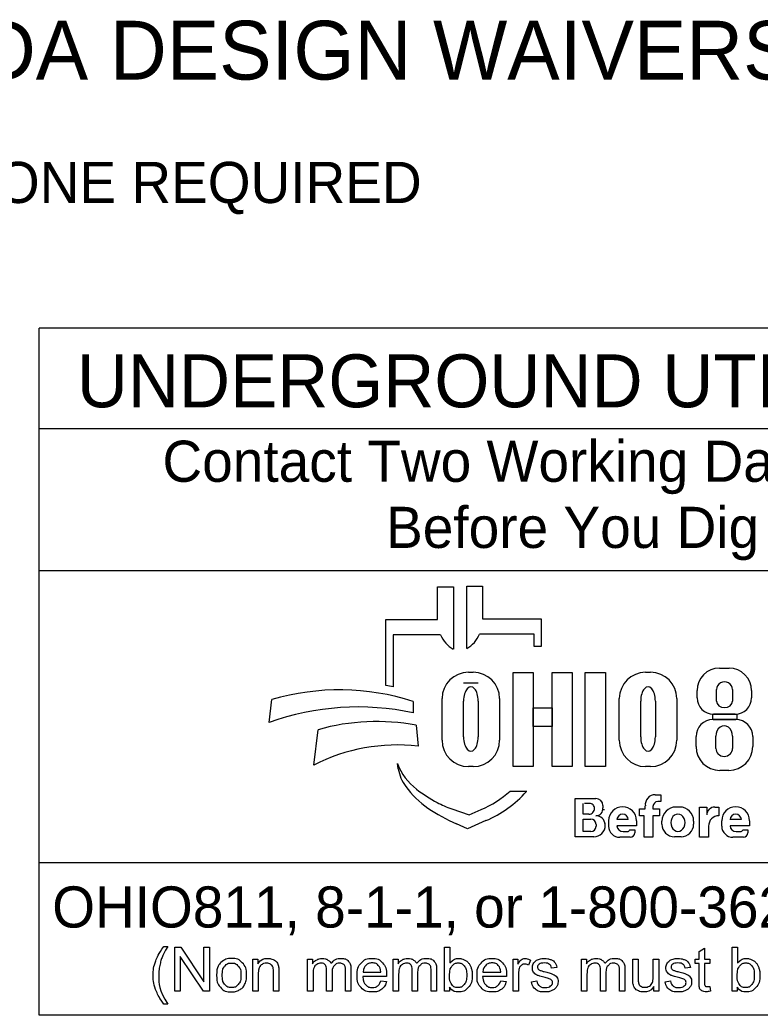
# Model space of a CAD drawing. Extents: x 0 to 48.6, y 0 to 22.
# Drawn here: x 2.312 to 4.831, y 2.143 to 5.529 of the extents above; entities that cross this region are included whole.
import ezdxf

# ---------------------------------------------------------------- set-up
doc = ezdxf.new("R2010")
doc.units = 0
doc.layers.add('SH_Data', color=7, linetype='Continuous')
doc.layers.add('SH_Text', color=7, linetype='Continuous')

msp = doc.modelspace()

# ---------------------------------------------------------------- linework, layer by layer
at = {"layer": 'SH_Data'}
for p, q in [((2.3775, 2.1428), (2.3775, 4.4803)), ((6.6275, 4.4803), (2.3775, 4.4803)), ((2.3775, 4.1387), (6.6275, 4.1387)), ((2.3775, 3.6553), (6.6275, 3.6553)), ((6.6275, 2.6607), (2.3775, 2.6607)), ((6.6275, 2.1428), (2.3775, 2.1428))]:
    msp.add_line(p, q, dxfattribs=at)
at = {"layer": 'SH_Text'}
for p, q in [((3.7335, 3.4883), (3.7335, 3.5998)), ((3.7335, 3.5998), (3.7872, 3.5998)), ((3.7872, 3.5998), (3.7872, 3.3877)), ((3.8329, 3.39), (3.8329, 3.6021)), ((3.8329, 3.6021), (3.8865, 3.6021)), ((3.8865, 3.6021), (3.8865, 3.4906)), ((3.5576, 3.2644), (3.5576, 3.4883)), ((3.5576, 3.4883), (3.7335, 3.4883)), ((3.8865, 3.4906), (4.0857, 3.4906)), ((4.0857, 3.4906), (4.0857, 3.3968)), ((3.5828, 3.4369), (3.5828, 3.26)), ((3.7439, 3.4369), (3.5828, 3.4369)), ((4.0625, 3.4392), (3.8761, 3.4392)), ((4.0625, 3.3968), (4.0625, 3.4392)), ((4.0857, 3.3968), (4.0625, 3.3968)), ((4.6931, 3.3231), (4.7258, 3.3231)), ((3.8385, 3.3091), (3.8551, 3.3091)), ((4.4416, 3.3091), (4.4581, 3.3091)), ((3.8718, 3.2721), (3.822, 3.2721)), ((4.683, 3.2111), (4.683, 3.2504)), ((4.7371, 3.2504), (4.7371, 3.2111)), ((3.7491, 3.0776), (3.7491, 3.2196)), ((3.9445, 3.2196), (3.9445, 3.0776)), ((4.3521, 3.0776), (4.3521, 3.2196)), ((4.5476, 3.2196), (4.5476, 3.0776)), ((4.6168, 3.2225), (4.6168, 3.2468)), ((4.8022, 3.2468), (4.8022, 3.2225)), ((3.1602, 3.1381), (3.1696, 3.2162)), ((3.6509, 3.2097), (3.6509, 3.1709)), ((3.822, 3.089), (3.822, 3.2114)), ((3.8718, 3.2114), (3.8718, 3.089)), ((4.425, 3.089), (4.425, 3.2114)), ((4.4748, 3.2114), (4.4748, 3.089)), ((4.7462, 3.1665), (4.6728, 3.1665)), ((3.6608, 3.1291), (3.6671, 3.0582)), ((4.671, 3.1482), (4.7483, 3.1482)), ((3.312, 2.9936), (3.3267, 3.1137)), ((4.6131, 3.0563), (4.6131, 3.0903)), ((4.6806, 3.0503), (4.6806, 3.0912)), ((4.7374, 3.0912), (4.7374, 3.0503)), ((4.8062, 3.0903), (4.8062, 3.0563)), ((3.5997, 2.9807), (3.5967, 2.9986)), ((3.8551, 2.9882), (3.8385, 2.9882)), ((4.4581, 2.9882), (4.4416, 2.9882)), ((4.7252, 2.9753), (4.6941, 2.9753)), ((3.98, 2.9048), (4.0375, 2.9048)), ((4.2013, 2.749), (4.2013, 2.8798)), ((4.2013, 2.8798), (4.2725, 2.8798)), ((4.4739, 2.8926), (4.4934, 2.8926)), ((4.4934, 2.8926), (4.4934, 2.8696)), ((3.7816, 2.8444), (3.841, 2.8239)), ((4.2293, 2.8263), (4.2293, 2.8632)), ((4.2545, 2.8632), (4.2332, 2.8632)), ((4.2963, 2.856), (4.2963, 2.8481)), ((4.4213, 2.8212), (4.4213, 2.8442)), ((4.4213, 2.8442), (4.4406, 2.8442)), ((4.4406, 2.8442), (4.4406, 2.8546)), ((4.4667, 2.8526), (4.4667, 2.8442)), ((4.4667, 2.8442), (4.4883, 2.8442)), ((4.4934, 2.8691), (4.4832, 2.8691)), ((4.4883, 2.8442), (4.4883, 2.8212)), ((4.5451, 2.8508), (4.5573, 2.8508)), ((4.6254, 2.7478), (4.6254, 2.8505)), ((4.6254, 2.8505), (4.6499, 2.8505)), ((4.6499, 2.8505), (4.6499, 2.8237)), ((4.6772, 2.8505), (4.691, 2.8505)), ((4.691, 2.8505), (4.691, 2.8209)), ((3.841, 2.8239), (3.8821, 2.8417)), ((4.2487, 2.8263), (4.2293, 2.8263)), ((4.4362, 2.8212), (4.4213, 2.8212)), ((4.4362, 2.7478), (4.4362, 2.8212)), ((4.4883, 2.8212), (4.4667, 2.8212)), ((4.4667, 2.8212), (4.4667, 2.7478)), ((3.835, 2.7769), (3.7976, 2.7934)), ((3.8983, 2.8044), (3.835, 2.7769)), ((4.2293, 2.7669), (4.2293, 2.8097)), ((4.2293, 2.8097), (4.2548, 2.8097)), ((4.2729, 2.7916), (4.2729, 2.7853)), ((4.3043, 2.7887), (4.3043, 2.7884)), ((4.3159, 2.7858), (4.3159, 2.8042)), ((4.3824, 2.8082), (4.3439, 2.8082)), ((4.4104, 2.7866), (4.344, 2.7866)), ((4.4104, 2.8042), (4.4104, 2.7866)), ((4.4973, 2.7922), (4.4973, 2.8029)), ((4.6051, 2.8029), (4.6051, 2.7922)), ((4.6559, 2.786), (4.6559, 2.7478)), ((4.7008, 2.7858), (4.7008, 2.8042)), ((4.7674, 2.8082), (4.7288, 2.8082)), ((4.7953, 2.7866), (4.7289, 2.7866)), ((4.7953, 2.8042), (4.7953, 2.7866)), ((4.265, 2.749), (4.2013, 2.749)), ((4.2546, 2.7669), (4.2293, 2.7669)), ((4.3892, 2.7478), (4.3538, 2.7478)), ((4.3649, 2.7673), (4.379, 2.7673)), ((4.3876, 2.7729), (4.4045, 2.7729)), ((4.4045, 2.7729), (4.4045, 2.7631)), ((4.4667, 2.7478), (4.4362, 2.7478)), ((4.5623, 2.7494), (4.5401, 2.7494)), ((4.6559, 2.7478), (4.6254, 2.7478)), ((4.7742, 2.7478), (4.7388, 2.7478)), ((4.7498, 2.7673), (4.7639, 2.7673)), ((4.7725, 2.7729), (4.7894, 2.7729)), ((4.7894, 2.7729), (4.7894, 2.7631))]:
    msp.add_line(p, q, dxfattribs=at)
for points in [[(3.991, 3.3081), (4.0589, 3.3081), (4.0589, 2.9881), (3.991, 2.9881)], [(4.1231, 3.3081), (4.1911, 3.3081), (4.1911, 2.9881), (4.1231, 2.9881)], [(4.2364, 3.3081), (4.3052, 3.3081), (4.3052, 2.9881), (4.2364, 2.9881)], [(4.0589, 3.1882), (4.1231, 3.1882), (4.1231, 3.1242), (4.0589, 3.1242)], [(4.6706, 3.1665), (4.7523, 3.1665), (4.7523, 3.1481), (4.6706, 3.1481)]]:
    msp.add_lwpolyline(points, close=True, dxfattribs=at)
for points in [[(2.8021, 2.3766), (2.8153, 2.3766)], [(2.8389, 2.2239), (2.8389, 2.3741), (2.8592, 2.3741), (2.9382, 2.2561), (2.9382, 2.3741), (2.9572, 2.3741), (2.9572, 2.2239), (2.9369, 2.2239), (2.8579, 2.3419), (2.8579, 2.2239), (2.8389, 2.2239)], [(3.7743, 2.2239), (3.7573, 2.2239), (3.7573, 2.3741), (3.7757, 2.3741), (3.7757, 2.3206)], [(4.6233, 2.2558), (4.6233, 2.3185), (4.6097, 2.3185), (4.6097, 2.3328), (4.6233, 2.3328), (4.6233, 2.3597), (4.6417, 2.3708), (4.6417, 2.3328), (4.6601, 2.3328), (4.6601, 2.3185), (4.6417, 2.3185), (4.6417, 2.2547)], [(4.7534, 2.2239), (4.7363, 2.2239), (4.7363, 2.3741), (4.7548, 2.3741), (4.7548, 2.3206)], [(3.1048, 2.2239), (3.1048, 2.3328), (3.1214, 2.3328), (3.1214, 2.3173)], [(3.2912, 2.2239), (3.2912, 2.3328), (3.3077, 2.3328), (3.3077, 2.3174)], [(3.5826, 2.2239), (3.5826, 2.3328), (3.5991, 2.3328), (3.5991, 2.3174)], [(3.9904, 2.2239), (3.9904, 2.3328), (4.007, 2.3328), (4.007, 2.3163)], [(4.0495, 2.3293), (4.043, 2.3122)], [(4.1394, 2.3046), (4.1213, 2.3022)], [(4.2236, 2.2239), (4.2236, 2.3328), (4.2401, 2.3328), (4.2401, 2.3174)], [(4.3979, 2.2654), (4.3979, 2.3328), (4.4164, 2.3328), (4.4164, 2.2724)], [(4.4676, 2.2745), (4.4676, 2.3328), (4.4861, 2.3328), (4.4861, 2.2239), (4.4696, 2.2239)], [(4.594, 2.3046), (4.5759, 2.3022)], [(3.1233, 2.2833), (3.1233, 2.2239), (3.1048, 2.2239)], [(3.1932, 2.2908), (3.1932, 2.2239), (3.1748, 2.2239), (3.1748, 2.2901)], [(3.3097, 2.2803), (3.3097, 2.2239), (3.2912, 2.2239)], [(3.3743, 2.2871), (3.3743, 2.2239), (3.3559, 2.2239), (3.3559, 2.2946)], [(3.4388, 2.2986), (3.4388, 2.2239), (3.4203, 2.2239), (3.4203, 2.2924)], [(3.56, 2.2736), (3.4788, 2.2736)], [(3.4799, 2.2887), (3.5406, 2.2887)], [(3.601, 2.2803), (3.601, 2.2239), (3.5826, 2.2239)], [(3.6657, 2.2871), (3.6657, 2.2239), (3.6473, 2.2239), (3.6473, 2.2946)], [(3.7301, 2.2986), (3.7301, 2.2239), (3.7117, 2.2239), (3.7117, 2.2924)], [(3.968, 2.2736), (3.8868, 2.2736)], [(3.8879, 2.2887), (3.9486, 2.2887)], [(4.0088, 2.2809), (4.0088, 2.2239), (3.9904, 2.2239)], [(4.242, 2.2803), (4.242, 2.2239), (4.2236, 2.2239)], [(4.3067, 2.2871), (4.3067, 2.2239), (4.2883, 2.2239), (4.2883, 2.2946)], [(4.3711, 2.2986), (4.3711, 2.2239), (4.3527, 2.2239), (4.3527, 2.2924)], [(3.5404, 2.2591), (3.5595, 2.2567)], [(3.7743, 2.2375), (3.7743, 2.2239)], [(3.9484, 2.2591), (3.9675, 2.2567)], [(4.053, 2.2564), (4.0712, 2.2593)], [(4.4696, 2.2239), (4.4696, 2.24)], [(4.5076, 2.2564), (4.5258, 2.2593)], [(4.6601, 2.2404), (4.6628, 2.2241)], [(4.7534, 2.2375), (4.7534, 2.2239)], [(2.8153, 2.1798), (2.8021, 2.1798)]]:
    msp.add_lwpolyline(points, dxfattribs=at)
for centre, radius, start, end in [((3.8353, 3.4736), 0.0985, 201.9296, 240.7469), ((3.7847, 3.476), 0.0985, 299.2531, 338.0704), ((4.6931, 3.2468), 0.0763, 90, 180), ((4.7258, 3.2468), 0.0763, 0, 90), ((3.8385, 3.2196), 0.0895, 90, 180), ((3.8551, 3.2196), 0.0895, 0, 90), ((4.4416, 3.2196), 0.0895, 90, 180), ((4.4581, 3.2196), 0.0895, 0, 90), ((3.4295, 2.4554), 0.8191, 79.2074, 81.0007), ((3.3997, 2.4302), 0.8191, 72.1402, 106.3144), ((4.6728, 3.2225), 0.056, 180, 270), ((4.7462, 3.2225), 0.056, 270, 0), ((3.4628, 2.2991), 0.8919, 77.8238, 109.8274), ((3.5267, 2.4094), 0.7322, 79.44, 105.8467), ((4.671, 3.0903), 0.0579, 90, 180), ((4.7483, 3.0903), 0.0579, 0, 90), ((3.5987, 2.4262), 0.6357, 83.8248, 116.8021), ((3.8385, 3.0776), 0.0895, 180, 270), ((3.8551, 3.0776), 0.0895, 270, 0), ((4.4416, 3.0776), 0.0895, 180, 270), ((4.4581, 3.0776), 0.0895, 270, 0), ((4.6941, 3.0563), 0.081, 180, 270), ((4.7252, 3.0563), 0.081, 270, 0), ((3.7841, 3.0707), 0.2008, 201.0457, 232.5314), ((3.741, 3.0048), 0.1433, 189.6817, 216.0884), ((3.8747, 3.1022), 0.3088, 216.0884, 235.7167), ((3.9766, 3.3219), 0.5173, 232.5314, 241.794), ((3.7387, 3.1722), 0.3602, 293.4582, 312.0712), ((3.7387, 3.1722), 0.401, 293.4582, 317.8286), ((4.2725, 2.856), 0.0238, 0, 90), ((4.4739, 2.859), 0.0335, 90, 187.5187), ((4.0412, 3.3465), 0.6044, 235.7167, 246.2325), ((3.8914, 3.1631), 0.3371, 241.794, 250.9821), ((4.2487, 2.845), 0.0187, 270, 2.0582), ((4.2505, 2.8463), 0.0169, 357.8325, 90), ((4.2721, 2.8453), 0.0243, 270, 6.6529), ((4.3631, 2.8042), 0.0473, 0, 180), ((4.4832, 2.8526), 0.0165, 90, 180), ((4.5451, 2.8029), 0.0478, 90, 180), ((4.5573, 2.8029), 0.0478, 0, 90), ((4.6768, 2.8237), 0.0269, 89.2449, 180), ((4.7481, 2.8042), 0.0473, 0, 180), ((4.2722, 2.7889), 0.0321, 4.0748, 90), ((4.2827, 2.8438), 0.0175, 347.4023, 0), ((4.3632, 2.8072), 0.0193, 2.9632, 177.0368), ((4.6908, 2.786), 0.0349, 89.6033, 180), ((4.7481, 2.8072), 0.0193, 2.9632, 177.0368), ((4.2546, 2.7853), 0.0184, 270, 0), ((4.2548, 2.7916), 0.0181, 0, 90), ((4.265, 2.7884), 0.0393, 270, 0), ((4.2714, 2.7887), 0.033, 0, 11.7502), ((4.3538, 2.7858), 0.038, 180, 270), ((4.3649, 2.7883), 0.021, 184.827, 270), ((4.5401, 2.7922), 0.0428, 180, 270), ((4.5623, 2.7922), 0.0428, 270, 0), ((4.7388, 2.7858), 0.038, 180, 270), ((4.7498, 2.7883), 0.021, 184.827, 270), ((4.379, 2.7767), 0.00938, 270, 335.9979), ((4.3892, 2.7631), 0.0152, 270, 0), ((4.7639, 2.7767), 0.00938, 270, 335.9979), ((4.7742, 2.7631), 0.0152, 270, 0)]:
    msp.add_arc(centre, radius, start, end, dxfattribs=at)
for centre, major_axis, ratio, start_param, end_param in [((3.8469, 3.2114), (0, 0.0484), 0.514403, 4.712389, 7.853982), ((4.4499, 3.2114), (0, 0.0484), 0.514403, 4.712389, 7.853982), ((4.71, 3.2504), (0.0271, 0), 0.969373, 0, 3.141593), ((4.71, 3.2111), (0.0271, 0), 0.818453, 3.141593, 6.283185), ((4.709, 3.0912), (0, 0.0358), 0.794529, 4.712389, 7.853982), ((3.8469, 3.089), (0, 0.0484), 0.514403, 1.570796, 4.712389), ((4.4499, 3.089), (0, 0.0484), 0.514403, 1.570796, 4.712389), ((4.709, 3.0503), (0.0284, 0), 0.959837, 3.141593, 6.283185), ((4.5517, 2.7976), (0, 0.029), 0.832186, 4.712389, 7.853982), ((4.5517, 2.7976), (0, 0.0302), 0.797287, 1.570796, 4.712389)]:
    msp.add_ellipse(centre, major_axis=major_axis, ratio=ratio, start_param=start_param, end_param=end_param, dxfattribs=at)
for points in [[(2.8021, 2.1798), (2.7869, 2.199), (2.7763, 2.2248), (2.7657, 2.2506), (2.7657, 2.2783), (2.7657, 2.3026), (2.7736, 2.325), (2.7829, 2.3509), (2.8021, 2.3766)], [(2.8153, 2.3766), (2.8029, 2.3553), (2.7989, 2.3462), (2.7927, 2.332), (2.7891, 2.3167), (2.7847, 2.2975), (2.7847, 2.2782), (2.7847, 2.2289), (2.8153, 2.1798)], [(2.9814, 2.2783), (2.9814, 2.3085), (2.9981, 2.3231), (3.0122, 2.3352), (3.0323, 2.3352), (3.0547, 2.3352), (3.069, 2.3205), (3.0832, 2.3058), (3.0832, 2.2799), (3.0832, 2.2589), (3.0769, 2.2469), (3.0706, 2.2348), (3.0586, 2.2282), (3.0466, 2.2215), (3.0323, 2.2215), (3.0095, 2.2215), (2.9954, 2.2362), (2.9814, 2.2508), (2.9814, 2.2783)], [(3.0003, 2.2783), (3.0003, 2.2574), (3.0094, 2.247), (3.0185, 2.2366), (3.0323, 2.2366), (3.046, 2.2366), (3.0551, 2.2471), (3.0642, 2.2575), (3.0642, 2.279), (3.0642, 2.2991), (3.0551, 2.3095), (3.0459, 2.3199), (3.0323, 2.3199), (3.0185, 2.3199), (3.0094, 2.3096), (3.0003, 2.2992), (3.0003, 2.2783)], [(3.1214, 2.3173), (3.1334, 2.3352), (3.156, 2.3352), (3.1659, 2.3352), (3.1741, 2.3316), (3.1823, 2.3281), (3.1864, 2.3224), (3.1905, 2.3166), (3.1922, 2.3087), (3.1932, 2.3036), (3.1932, 2.2908)], [(3.1748, 2.2901), (3.1748, 2.3013), (3.1726, 2.3069), (3.1705, 2.3125), (3.165, 2.3158), (3.1595, 2.3191), (3.1521, 2.3191), (3.1404, 2.3191), (3.1318, 2.3117), (3.1233, 2.3042), (3.1233, 2.2833)], [(3.3077, 2.3174), (3.3128, 2.3254), (3.3214, 2.3303), (3.3299, 2.3352), (3.3407, 2.3352), (3.3528, 2.3352), (3.3606, 2.3301), (3.3683, 2.3251), (3.3715, 2.3161), (3.3844, 2.3352), (3.4051, 2.3352), (3.4213, 2.3352), (3.43, 2.3262), (3.4388, 2.3172), (3.4388, 2.2986)], [(3.3559, 2.2946), (3.3559, 2.3069), (3.3514, 2.313), (3.3469, 2.3191), (3.3366, 2.3191), (3.3288, 2.3191), (3.3222, 2.315), (3.3156, 2.311), (3.3126, 2.3031), (3.3097, 2.2952), (3.3097, 2.2803)], [(3.4203, 2.2924), (3.4203, 2.3035), (3.4185, 2.3083), (3.4168, 2.3132), (3.412, 2.3162), (3.4073, 2.3191), (3.401, 2.3191), (3.3895, 2.3191), (3.3819, 2.3115), (3.3743, 2.3039), (3.3743, 2.2871)], [(3.5595, 2.2567), (3.555, 2.24), (3.5428, 2.2307), (3.5306, 2.2215), (3.5117, 2.2215), (3.4878, 2.2215), (3.4738, 2.2362), (3.4598, 2.2509), (3.4598, 2.2774), (3.4598, 2.3049), (3.474, 2.32), (3.4881, 2.3352), (3.5106, 2.3352), (3.5324, 2.3352), (3.5463, 2.3203), (3.5601, 2.3055), (3.5601, 2.2785), (3.5601, 2.2769), (3.56, 2.2736)], [(3.5406, 2.2887), (3.5394, 2.3025), (3.5337, 2.3094), (3.5249, 2.3201), (3.5108, 2.3201), (3.4981, 2.3201), (3.4894, 2.3115), (3.4808, 2.303), (3.4799, 2.2887)], [(3.5991, 2.3174), (3.6042, 2.3254), (3.6127, 2.3303), (3.6212, 2.3352), (3.6321, 2.3352), (3.6442, 2.3352), (3.6519, 2.3301), (3.6597, 2.3251), (3.6628, 2.3161), (3.6758, 2.3352), (3.6965, 2.3352), (3.7127, 2.3352), (3.7214, 2.3262), (3.7301, 2.3172), (3.7301, 2.2986)], [(3.6473, 2.2946), (3.6473, 2.3069), (3.6428, 2.313), (3.6383, 2.3191), (3.628, 2.3191), (3.6202, 2.3191), (3.6136, 2.315), (3.607, 2.311), (3.604, 2.3031), (3.601, 2.2952), (3.601, 2.2803)], [(3.7117, 2.2924), (3.7117, 2.3035), (3.7099, 2.3083), (3.7081, 2.3132), (3.7034, 2.3162), (3.6987, 2.3191), (3.6923, 2.3191), (3.6809, 2.3191), (3.6733, 2.3115), (3.6657, 2.3039), (3.6657, 2.2871)], [(3.7741, 2.2792), (3.7741, 2.2596), (3.7794, 2.2509), (3.7881, 2.2366), (3.8029, 2.2366), (3.815, 2.2366), (3.8238, 2.2471), (3.8326, 2.2576), (3.8326, 2.2784), (3.8326, 2.2998), (3.8241, 2.3099), (3.8157, 2.3201), (3.8038, 2.3201), (3.7917, 2.3201), (3.7829, 2.3096), (3.7741, 2.299), (3.7741, 2.2792)], [(3.7757, 2.3206), (3.7874, 2.3352), (3.8055, 2.3352), (3.8155, 2.3352), (3.8245, 2.3311), (3.8335, 2.3271), (3.8392, 2.3198), (3.845, 2.3124), (3.8483, 2.3021), (3.8516, 2.2918), (3.8516, 2.28), (3.8516, 2.252), (3.8378, 2.2368), (3.8239, 2.2215), (3.8046, 2.2215), (3.7853, 2.2215), (3.7743, 2.2375)], [(3.9675, 2.2567), (3.963, 2.24), (3.9508, 2.2307), (3.9386, 2.2215), (3.9196, 2.2215), (3.8958, 2.2215), (3.8818, 2.2362), (3.8678, 2.2509), (3.8678, 2.2774), (3.8678, 2.3049), (3.882, 2.32), (3.8961, 2.3352), (3.9186, 2.3352), (3.9404, 2.3352), (3.9543, 2.3203), (3.9681, 2.3055), (3.9681, 2.2785), (3.9681, 2.2769), (3.968, 2.2736)], [(3.9486, 2.2887), (3.9474, 2.3025), (3.9417, 2.3094), (3.9328, 2.3201), (3.9188, 2.3201), (3.9061, 2.3201), (3.8974, 2.3115), (3.8888, 2.303), (3.8879, 2.2887)], [(4.007, 2.3163), (4.0133, 2.3278), (4.0187, 2.3315), (4.0241, 2.3352), (4.0305, 2.3352), (4.0398, 2.3352), (4.0495, 2.3293)], [(4.043, 2.3122), (4.0363, 2.3162), (4.0295, 2.3162), (4.0235, 2.3162), (4.0187, 2.3125), (4.0139, 2.3089), (4.0119, 2.3024), (4.0088, 2.2926), (4.0088, 2.2809)], [(4.1213, 2.3022), (4.1201, 2.3106), (4.1142, 2.3153), (4.1083, 2.3201), (4.0975, 2.3201), (4.0848, 2.3201), (4.0794, 2.3159), (4.0739, 2.3116), (4.0739, 2.306), (4.0739, 2.3024), (4.0762, 2.2995), (4.0785, 2.2966), (4.0833, 2.2946), (4.086, 2.2936), (4.0996, 2.2899), (4.1192, 2.2847), (4.1269, 2.2813), (4.1347, 2.278), (4.1391, 2.2717), (4.1435, 2.2653), (4.1435, 2.2559), (4.1435, 2.2467), (4.1381, 2.2386), (4.1327, 2.2304), (4.1226, 2.226), (4.1124, 2.2215), (4.0996, 2.2215), (4.0784, 2.2215), (4.0672, 2.2303), (4.0561, 2.2391), (4.053, 2.2564)], [(4.0712, 2.2593), (4.0727, 2.2483), (4.0798, 2.2425), (4.0868, 2.2366), (4.0995, 2.2366), (4.1122, 2.2366), (4.1184, 2.2418), (4.1245, 2.247), (4.1245, 2.254), (4.1245, 2.2602), (4.1191, 2.2638), (4.1153, 2.2663), (4.1002, 2.2701), (4.0799, 2.2752), (4.072, 2.2789), (4.0642, 2.2827), (4.0601, 2.2893), (4.0561, 2.2959), (4.0561, 2.3038), (4.0561, 2.3111), (4.0594, 2.3173), (4.0628, 2.3235), (4.0685, 2.3276), (4.0728, 2.3308), (4.0803, 2.333), (4.0877, 2.3352), (4.0962, 2.3352), (4.109, 2.3352), (4.1187, 2.3315), (4.1284, 2.3278), (4.133, 2.3215), (4.1377, 2.3152), (4.1394, 2.3046)], [(4.2401, 2.3174), (4.2452, 2.3254), (4.2537, 2.3303), (4.2622, 2.3352), (4.2731, 2.3352), (4.2852, 2.3352), (4.2929, 2.3301), (4.3007, 2.3251), (4.3038, 2.3161), (4.3168, 2.3352), (4.3375, 2.3352), (4.3537, 2.3352), (4.3624, 2.3262), (4.3711, 2.3172), (4.3711, 2.2986)], [(4.2883, 2.2946), (4.2883, 2.3069), (4.2838, 2.313), (4.2793, 2.3191), (4.269, 2.3191), (4.2612, 2.3191), (4.2546, 2.315), (4.248, 2.311), (4.245, 2.3031), (4.242, 2.2952), (4.242, 2.2803)], [(4.3527, 2.2924), (4.3527, 2.3035), (4.3509, 2.3083), (4.3491, 2.3132), (4.3444, 2.3162), (4.3397, 2.3191), (4.3333, 2.3191), (4.3219, 2.3191), (4.3143, 2.3115), (4.3067, 2.3039), (4.3067, 2.2871)], [(4.5759, 2.3022), (4.5747, 2.3106), (4.5688, 2.3153), (4.5629, 2.3201), (4.5521, 2.3201), (4.5394, 2.3201), (4.5339, 2.3159), (4.5285, 2.3116), (4.5285, 2.306), (4.5285, 2.3024), (4.5308, 2.2995), (4.533, 2.2966), (4.5378, 2.2946), (4.5406, 2.2936), (4.5542, 2.2899), (4.5737, 2.2847), (4.5815, 2.2813), (4.5893, 2.278), (4.5937, 2.2717), (4.5981, 2.2653), (4.5981, 2.2559), (4.5981, 2.2467), (4.5927, 2.2386), (4.5873, 2.2304), (4.5772, 2.226), (4.567, 2.2215), (4.5542, 2.2215), (4.5329, 2.2215), (4.5218, 2.2303), (4.5107, 2.2391), (4.5076, 2.2564)], [(4.5258, 2.2593), (4.5273, 2.2483), (4.5343, 2.2425), (4.5414, 2.2366), (4.554, 2.2366), (4.5668, 2.2366), (4.5729, 2.2418), (4.5791, 2.247), (4.5791, 2.254), (4.5791, 2.2602), (4.5736, 2.2638), (4.5698, 2.2663), (4.5548, 2.2701), (4.5345, 2.2752), (4.5266, 2.2789), (4.5188, 2.2827), (4.5147, 2.2893), (4.5107, 2.2959), (4.5107, 2.3038), (4.5107, 2.3111), (4.514, 2.3173), (4.5173, 2.3235), (4.5231, 2.3276), (4.5274, 2.3308), (4.5348, 2.333), (4.5423, 2.3352), (4.5508, 2.3352), (4.5636, 2.3352), (4.5733, 2.3315), (4.583, 2.3278), (4.5876, 2.3215), (4.5922, 2.3152), (4.594, 2.3046)], [(4.7532, 2.2792), (4.7532, 2.2596), (4.7585, 2.2509), (4.7672, 2.2366), (4.782, 2.2366), (4.7941, 2.2366), (4.8029, 2.2471), (4.8116, 2.2576), (4.8116, 2.2784), (4.8116, 2.2998), (4.8032, 2.3099), (4.7948, 2.3201), (4.7828, 2.3201), (4.7708, 2.3201), (4.762, 2.3096), (4.7532, 2.299), (4.7532, 2.2792)], [(4.7548, 2.3206), (4.7664, 2.3352), (4.7846, 2.3352), (4.7946, 2.3352), (4.8036, 2.3311), (4.8125, 2.3271), (4.8183, 2.3198), (4.8241, 2.3124), (4.8274, 2.3021), (4.8306, 2.2918), (4.8306, 2.28), (4.8306, 2.252), (4.8168, 2.2368), (4.803, 2.2215), (4.7836, 2.2215), (4.7644, 2.2215), (4.7534, 2.2375)], [(3.4788, 2.2736), (3.4799, 2.2557), (3.489, 2.2462), (3.4981, 2.2366), (3.5117, 2.2366), (3.5219, 2.2366), (3.5291, 2.242), (3.5362, 2.2473), (3.5404, 2.2591)], [(3.8868, 2.2736), (3.8879, 2.2557), (3.897, 2.2462), (3.9061, 2.2366), (3.9197, 2.2366), (3.9299, 2.2366), (3.937, 2.242), (3.9442, 2.2473), (3.9484, 2.2591)], [(4.4164, 2.2724), (4.4164, 2.258), (4.4175, 2.253), (4.4192, 2.2457), (4.4249, 2.2416), (4.4305, 2.2374), (4.4388, 2.2374), (4.4471, 2.2374), (4.4543, 2.2417), (4.4616, 2.2459), (4.4646, 2.2533), (4.4676, 2.2606), (4.4676, 2.2745)], [(4.4696, 2.24), (4.4569, 2.2215), (4.4351, 2.2215), (4.4255, 2.2215), (4.4171, 2.2252), (4.4088, 2.2289), (4.4047, 2.2345), (4.4007, 2.2401), (4.3991, 2.2482), (4.3979, 2.2536), (4.3979, 2.2654)], [(4.6628, 2.2241), (4.655, 2.2224), (4.6488, 2.2224), (4.6388, 2.2224), (4.6333, 2.2256), (4.6278, 2.2288), (4.6255, 2.234), (4.6233, 2.2392), (4.6233, 2.2558)], [(4.6417, 2.2547), (4.6417, 2.2468), (4.6427, 2.2445), (4.6436, 2.2423), (4.6458, 2.2409), (4.648, 2.2396), (4.6521, 2.2396), (4.6551, 2.2396), (4.6601, 2.2404)]]:
    msp.add_open_spline(points, degree=3, dxfattribs=at)

# ---------------------------------------------------------------- texts
for s, height, p in [('ADA DESIGN WAIVERS', 0.2, (1.9944, 5.3256)), ('  NONE REQUIRED                          ', 0.14, (1.9944, 4.9056)), ('UNDERGROUND UTILITIES', 0.18, (2.5057, 4.2106)), ('Contact Two Working Days', 0.14, (2.7972, 3.9571)), ('Before You Dig', 0.14, (3.5583, 3.7321)), ('OHIO811, 8-1-1, or 1-800-362-2764', 0.14, (2.422, 2.4406))]:
    msp.add_text(s, height=height, dxfattribs=at).set_placement(p)

doc.saveas('drawing.dxf')
